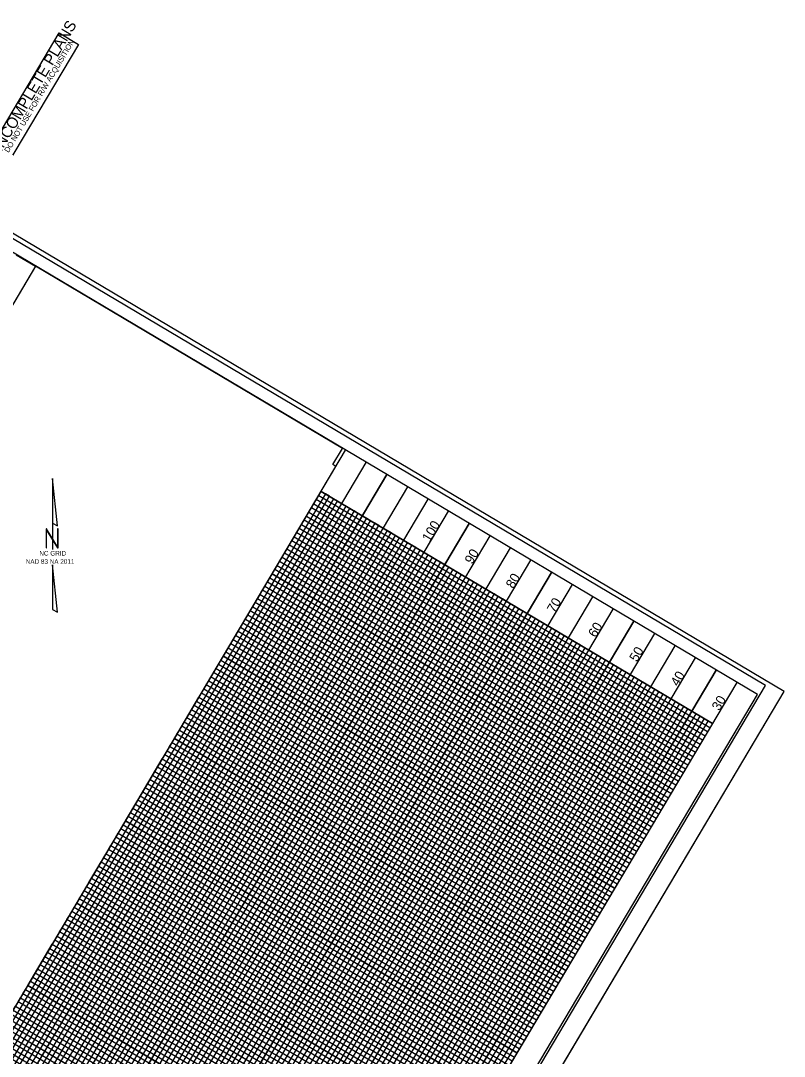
# Model space of a CAD drawing. Extents: x 2138768 to 2143723, y 406633 to 414335.
# Drawn here: x 2141936 to 2142733, y 411305 to 412387 of the extents above; entities that cross this region are included whole.
import ezdxf

# ---------------------------------------------------------------- set-up
doc = ezdxf.new("R2010")
doc.units = 0
for name, color, linetype in [('CTL North Arrow NAD 83 NA 2011 CELL', 7, 'Continuous'), ('Exist Vertical Profile Vertical Axis Label', 7, 'Continuous'), ('Sheet Clip Boundary CELL', 7, 'Continuous'), ('Sheet Cutting Line CELL', 7, 'Continuous'), ('Sheet DOT Grid CELL', 7, 'Continuous'), ('Sheet Layout Profile Border Port 2', 7, 'Continuous'), ('Sheet Plan And Profile CELL', 7, 'Continuous'), ('Sheet Plot Border Inside CELL', 7, 'Continuous'), ('Sheet Plot Border Outside CELL', 7, 'Continuous'), ('Sheet Profile Grid Major CELL', 7, 'Continuous'), ('Sheet Profile Grid Middle CELL', 7, 'Continuous'), ('Sheet Profile Grid Minor CELL', 7, 'Continuous'), ('Sheet Sticker Exception Certification CELL', 7, 'Continuous'), ('Sheet Sticker Incomplete CELL', 7, 'Continuous')]:
    doc.layers.add(name, color=color, linetype=linetype)

msp = doc.modelspace()

# ---------------------------------------------------------------- linework, layer by layer
at = {"layer": 'CTL North Arrow NAD 83 NA 2011 CELL'}
msp.add_line((2141969.1, 411838.7), (2141969.1, 411838.7), dxfattribs=at)
for points in [[(2141969, 411908.5), (2141969, 411861.9), (2141974.5, 411859.1)], [(2141962.4, 411836.1), (2141963, 411836.1), (2141963, 411854.8), (2141974.5, 411836.1), (2141975.1, 411836.1), (2141975.1, 411855.9), (2141974.5, 411855.9), (2141974.5, 411837.2), (2141963, 411855.9), (2141962.4, 411855.9)], [(2141969, 411771.9), (2141974.5, 411769.1), (2141969, 411818.5)]]:
    msp.add_lwpolyline(points, close=True, dxfattribs=at)
msp.add_lwpolyline([(2141969, 411861.9), (2141969, 411834.4)], dxfattribs=at)
at = {"layer": 'Sheet Clip Boundary CELL'}
msp.add_lwpolyline([(2141532, 410686.1), (2141538.9, 410697.6), (2142265.1, 411921.2), (2142261.9, 411923.1), (2142271.9, 411940), (2141951.4, 412130.3), (2141849.3, 411958.2), (2141755.1, 412014.2), (2141652.8, 411841.9), (2141597.8, 411874.5), (2141065.9, 410978.3)], close=True, dxfattribs=at)
at = {"layer": 'Sheet Cutting Line CELL'}
msp.add_line((2141873.9, 410238.4), (2142733.2, 411686.1), dxfattribs=at)
at = {"layer": 'Sheet DOT Grid CELL'}
for p, q in [((2141509.6, 410648.2), (2142275.2, 411938.1)), ((2141552.6, 410622.7), (2142318.2, 411912.6)), ((2142249.7, 411895.1), (2142658.1, 411652.7)), ((2141595.6, 410597.2), (2142361.2, 411887.1)), ((2141638.6, 410571.7), (2142404.2, 411861.6)), ((2142224.1, 411852.1), (2142632.6, 411609.7)), ((2141681.6, 410546.1), (2142447.2, 411836.1)), ((2141724.5, 410520.6), (2142490.2, 411810.5)), ((2142198.6, 411809.1), (2142607.1, 411566.7)), ((2141767.5, 410495.1), (2142533.2, 411785)), ((2141810.5, 410469.6), (2142576.1, 411759.5)), ((2142173.1, 411766.1), (2142581.6, 411523.7)), ((2141853.5, 410444.1), (2142619.1, 411734)), ((2142147.6, 411723.1), (2142556, 411480.7)), ((2141896.5, 410418.5), (2142662.1, 411708.5)), ((2142122, 411680.2), (2142530.5, 411437.7)), ((2142096.5, 411637.2), (2142505, 411394.7)), ((2142071, 411594.2), (2142479.5, 411351.7)), ((2142045.5, 411551.2), (2142454, 411308.7)), ((2142020, 411508.2), (2142428.4, 411265.7)), ((2141994.4, 411465.2), (2142402.9, 411222.7)), ((2141968.9, 411422.2), (2142377.4, 411179.7)), ((2141943.4, 411379.2), (2142351.9, 411136.7)), ((2141917.9, 411336.2), (2142326.4, 411093.7))]:
    msp.add_line(p, q, dxfattribs=at)
at = {"layer": 'Sheet Layout Profile Border Port 2'}
msp.add_lwpolyline([(2141535.1, 410691.2), (2142249.7, 411895.1), (2142658.1, 411652.7), (2141943.6, 410448.8)], close=True, dxfattribs=at)
at = {"layer": 'Sheet Plan And Profile CELL'}
msp.add_line((2142683.6, 411695.7), (2141918, 410405.8), dxfattribs=at)
msp.add_lwpolyline([(2141802.2, 412218.9), (2141036.6, 410929), (2141939.5, 410393), (2142705.1, 411682.9)], close=True, dxfattribs=at)
at = {"layer": 'Sheet Plot Border Inside CELL'}
msp.add_lwpolyline([(2141863.3, 410259.8), (2142713.7, 411692.4), (2141806.4, 412230.9), (2140956.1, 410798.2)], close=True, dxfattribs=at)
at = {"layer": 'Sheet Plot Border Outside CELL'}
msp.add_lwpolyline([(2141873.9, 410238.4), (2142733.2, 411686.1), (2141791.5, 412245), (2140932.3, 410797.3)], close=True, dxfattribs=at)
at = {"layer": 'Sheet Profile Grid Major CELL'}
for points in [[(2141509.6, 410648.2), (2142275.2, 411938.1)], [(2142318.2, 411912.6), (2141552.6, 410622.7), (2141595.6, 410597.2), (2142361.2, 411887.1)], [(2142658.1, 411652.7), (2142249.7, 411895.1)], [(2142404.2, 411861.6), (2141638.6, 410571.7), (2141681.6, 410546.1), (2142447.2, 411836.1)], [(2142607.1, 411566.7), (2142198.6, 411809.1), (2142224.1, 411852.1), (2142632.6, 411609.7)], [(2142490.2, 411810.5), (2141724.5, 410520.6), (2141767.5, 410495.1), (2142533.2, 411785)], [(2142576.1, 411759.5), (2141810.5, 410469.6), (2141853.5, 410444.1), (2142619.1, 411734)], [(2142556, 411480.7), (2142147.6, 411723.1), (2142173.1, 411766.1), (2142581.6, 411523.7)], [(2142662.1, 411708.5), (2141896.5, 410418.5)], [(2142505, 411394.7), (2142096.5, 411637.2), (2142122, 411680.2), (2142530.5, 411437.7)], [(2142454, 411308.7), (2142045.5, 411551.2), (2142071, 411594.2), (2142479.5, 411351.7)], [(2142402.9, 411222.7), (2141994.4, 411465.2), (2142020, 411508.2), (2142428.4, 411265.7)], [(2142351.9, 411136.7), (2141943.4, 411379.2), (2141968.9, 411422.2), (2142377.4, 411179.7)], [(2142300.8, 411050.7), (2141892.4, 411293.2), (2141917.9, 411336.2), (2142326.4, 411093.7)]]:
    msp.add_lwpolyline(points, dxfattribs=at)
at = {"layer": 'Sheet Profile Grid Middle CELL'}
for p, q in [((2141531.1, 410635.5), (2142296.7, 411925.4)), ((2142339.7, 411899.9), (2141574.1, 410609.9)), ((2141617.1, 410584.4), (2142382.7, 411874.3)), ((2142425.7, 411848.8), (2141660.1, 410558.9)), ((2141703.1, 410533.4), (2142468.7, 411823.3)), ((2142511.7, 411797.8), (2141746, 410507.9)), ((2141789, 410482.3), (2142554.6, 411772.3)), ((2142597.6, 411746.7), (2141832, 410456.8)), ((2141875, 410431.3), (2142640.6, 411721.2))]:
    msp.add_line(p, q, dxfattribs=at)
for points in [[(2142619.8, 411588.2), (2142211.4, 411830.6), (2142236.9, 411873.6), (2142645.4, 411631.2)], [(2142568.8, 411502.2), (2142160.3, 411744.6), (2142185.9, 411787.6), (2142594.3, 411545.2)], [(2142517.8, 411416.2), (2142109.3, 411658.7), (2142134.8, 411701.6), (2142543.3, 411459.2)], [(2142466.7, 411330.2), (2142058.2, 411572.7), (2142083.8, 411615.7), (2142492.2, 411373.2)], [(2142415.7, 411244.2), (2142007.2, 411486.7), (2142032.7, 411529.7), (2142441.2, 411287.2)], [(2142364.6, 411158.2), (2141956.2, 411400.7), (2141981.7, 411443.7), (2142390.2, 411201.2)], [(2142313.6, 411072.2), (2141905.1, 411314.7), (2141930.6, 411357.7), (2142339.1, 411115.2)]]:
    msp.add_lwpolyline(points, dxfattribs=at)
at = {"layer": 'Sheet Profile Grid Minor CELL'}
for points in [[(2141543.7, 410686.1), (2142258.3, 411890), (2142254, 411892.6), (2141539.4, 410688.7)], [(2142653, 411644.1), (2142244.5, 411886.5), (2142247.1, 411890.8), (2142655.6, 411648.4)], [(2141552.3, 410681), (2142266.8, 411884.9), (2142262.5, 411887.5), (2141548, 410683.6)], [(2141565.2, 410673.4), (2142279.7, 411877.3), (2142275.4, 411879.8), (2141560.9, 410675.9)], [(2142647.9, 411635.5), (2142239.4, 411877.9), (2142242, 411882.2), (2142650.5, 411639.8)], [(2141573.8, 410668.3), (2142288.3, 411872.2), (2142284, 411874.7), (2141569.5, 410670.8)], [(2142640.3, 411622.6), (2142231.8, 411865), (2142234.3, 411869.3), (2142642.8, 411626.9)], [(2141586.7, 410660.6), (2142301.2, 411864.5), (2142296.9, 411867.1), (2141582.4, 410663.2)], [(2141595.3, 410655.5), (2142309.8, 411859.4), (2142305.5, 411862), (2141591, 410658.1)], [(2142635.2, 411614), (2142226.7, 411856.4), (2142229.2, 411860.7), (2142637.7, 411618.3)], [(2141608.2, 410647.8), (2142322.7, 411851.8), (2142318.4, 411854.3), (2141603.9, 410650.4)], [(2141616.8, 410642.7), (2142331.3, 411846.6), (2142327, 411849.2), (2141612.5, 410645.3)], [(2142627.5, 411601.1), (2142219, 411843.5), (2142221.6, 411847.8), (2142630, 411605.4)], [(2141625.4, 410637.6), (2142339.9, 411841.5)], [(2141634, 410632.5), (2142348.5, 411836.4), (2142344.2, 411839), (2141629.7, 410635.1)], [(2142622.4, 411592.5), (2142213.9, 411834.9), (2142216.5, 411839.2), (2142624.9, 411596.8)], [(2141646.9, 410624.9), (2142361.4, 411828.8), (2142352.8, 411833.9), (2141638.3, 410630)], [(2141655.5, 410619.8), (2142370, 411823.7), (2142365.7, 411826.2), (2141651.2, 410622.3)], [(2142614.7, 411579.6), (2142206.3, 411822), (2142208.8, 411826.3), (2142617.3, 411583.9)], [(2141668.4, 410612.1), (2142382.9, 411816), (2142374.3, 411821.1), (2141659.8, 410617.2)], [(2142609.6, 411571), (2142201.2, 411813.4), (2142203.7, 411817.7), (2142612.2, 411575.3)], [(2141677, 410607), (2142391.5, 411810.9), (2142387.2, 411813.5), (2141672.7, 410609.6)], [(2141689.9, 410599.4), (2142404.4, 411803.3), (2142395.8, 411808.4), (2141681.3, 410604.5)], [(2142602, 411558.1), (2142193.5, 411800.5), (2142196.1, 411804.8), (2142604.5, 411562.4)], [(2141698.5, 410594.2), (2142413, 411798.2), (2142408.7, 411800.7), (2141694.2, 410596.8)], [(2141711.4, 410586.6), (2142425.9, 411790.5), (2142417.3, 411795.6), (2141702.8, 410591.7)], [(2142596.9, 411549.5), (2142188.4, 411791.9), (2142191, 411796.2), (2142599.4, 411553.8)], [(2141720, 410581.5), (2142434.5, 411785.4), (2142430.2, 411788), (2141715.7, 410584)], [(2141732.9, 410573.8), (2142447.4, 411777.7), (2142438.8, 411782.8), (2141724.3, 410578.9)], [(2142589.2, 411536.6), (2142180.7, 411779), (2142183.3, 411783.3), (2142591.8, 411540.9)], [(2141741.5, 410568.7), (2142456, 411772.6), (2142451.7, 411775.2), (2141737.2, 410571.3)], [(2142584.1, 411528), (2142175.6, 411770.4), (2142178.2, 411774.7), (2142586.7, 411532.3)], [(2141754.4, 410561.1), (2142468.9, 411765), (2142460.3, 411770.1), (2141745.8, 410566.2)], [(2141763, 410556), (2142477.5, 411759.9), (2142473.2, 411762.4), (2141758.7, 410558.5)], [(2142576.5, 411515.1), (2142168, 411757.5), (2142170.5, 411761.8), (2142579, 411519.4)], [(2141775.9, 410548.3), (2142490.4, 411752.2), (2142481.8, 411757.3), (2141767.3, 410553.4)], [(2141784.5, 410543.2), (2142499, 411747.1), (2142494.7, 411749.7), (2141780.2, 410545.8)], [(2142571.4, 411506.5), (2142162.9, 411748.9), (2142165.4, 411753.2), (2142573.9, 411510.8)], [(2141797.4, 410535.6), (2142511.9, 411739.5), (2142503.3, 411744.6), (2141788.8, 410540.7)], [(2142563.7, 411493.6), (2142155.2, 411736), (2142157.8, 411740.3), (2142566.2, 411497.9)], [(2141806, 410530.4), (2142520.5, 411734.4), (2142516.2, 411736.9), (2141801.7, 410533)], [(2141818.9, 410522.8), (2142533.4, 411726.7), (2142524.8, 411731.8), (2141810.3, 410527.9)], [(2142558.6, 411485), (2142150.1, 411727.4), (2142152.7, 411731.7), (2142561.1, 411489.3)], [(2141827.5, 410517.7), (2142542, 411721.6), (2142537.7, 411724.1), (2141823.2, 410520.2)], [(2141840.4, 410510), (2142554.9, 411713.9), (2142546.3, 411719), (2141831.8, 410515.1)], [(2142550.9, 411472.1), (2142142.5, 411714.5), (2142145, 411718.8), (2142553.5, 411476.4)], [(2141849, 410504.9), (2142563.5, 411708.8), (2142559.2, 411711.4), (2141844.7, 410507.5)], [(2141861.9, 410497.3), (2142576.4, 411701.2), (2142567.8, 411706.3), (2141853.3, 410502.4)], [(2142545.8, 411463.5), (2142137.4, 411705.9), (2142139.9, 411710.2), (2142548.4, 411467.8)], [(2141870.5, 410492.2), (2142585, 411696.1), (2142580.7, 411698.6), (2141866.2, 410494.7)], [(2142538.2, 411450.6), (2142129.7, 411693.1), (2142132.3, 411697.4), (2142540.7, 411454.9)], [(2141883.4, 410484.5), (2142597.9, 411688.4), (2142589.3, 411693.5), (2141874.8, 410489.6)], [(2141939.3, 410451.3), (2142653.8, 411655.2), (2142649.5, 411657.8), (2141935, 410453.9), (2141930.7, 410456.4), (2142645.2, 411660.3), (2142640.9, 411662.9), (2141926.4, 410459), (2141922.1, 410461.5), (2141917.8, 410464.1), (2142632.3, 411668), (2142628, 411670.6), (2141913.5, 410466.6), (2141909.2, 410469.2), (2142623.7, 411673.1), (2142619.4, 411675.7), (2141904.9, 410471.8), (2141900.6, 410474.3), (2141896.3, 410476.9), (2142610.8, 411680.8), (2142606.5, 411683.3), (2141892, 410479.4), (2141887.7, 410482), (2142602.2, 411685.9)], [(2142533.1, 411442), (2142124.6, 411684.5), (2142127.2, 411688.8), (2142535.6, 411446.3)], [(2142525.4, 411429.1), (2142116.9, 411671.6), (2142119.5, 411675.9), (2142528, 411433.4)], [(2142520.3, 411420.5), (2142111.8, 411663), (2142114.4, 411667.3), (2142522.9, 411424.8)], [(2142512.7, 411407.6), (2142104.2, 411650.1), (2142106.7, 411654.4), (2142515.2, 411411.9)], [(2142507.6, 411399), (2142099.1, 411641.5), (2142101.6, 411645.8), (2142510.1, 411403.3)], [(2142499.9, 411386.1), (2142091.4, 411628.6), (2142094, 411632.9), (2142502.4, 411390.4)], [(2142494.8, 411377.5), (2142086.3, 411620), (2142088.9, 411624.3), (2142497.3, 411381.8)], [(2142487.1, 411364.6), (2142078.7, 411607.1), (2142081.2, 411611.4), (2142489.7, 411368.9)], [(2142482, 411356), (2142073.6, 411598.5), (2142076.1, 411602.8), (2142484.6, 411360.3)], [(2142474.4, 411343.1), (2142065.9, 411585.6), (2142068.5, 411589.9), (2142476.9, 411347.4)], [(2142469.3, 411334.5), (2142060.8, 411577), (2142063.4, 411581.3), (2142471.8, 411338.8)], [(2142461.6, 411321.6), (2142053.1, 411564.1), (2142055.7, 411568.4), (2142464.2, 411325.9)], [(2142456.5, 411313), (2142048, 411555.5), (2142050.6, 411559.8), (2142459.1, 411317.3)], [(2142448.9, 411300.1), (2142040.4, 411542.6), (2142042.9, 411546.9), (2142451.4, 411304.4)], [(2142443.8, 411291.5), (2142035.3, 411534), (2142037.8, 411538.3), (2142446.3, 411295.8)], [(2142436.1, 411278.6), (2142027.6, 411521.1), (2142030.2, 411525.4), (2142438.6, 411282.9)], [(2142431, 411270), (2142022.5, 411512.5), (2142025.1, 411516.8), (2142433.5, 411274.3)], [(2142423.3, 411257.1), (2142014.9, 411499.6), (2142017.4, 411503.9), (2142425.9, 411261.4)], [(2142418.2, 411248.5), (2142009.8, 411491), (2142012.3, 411495.3), (2142420.8, 411252.8)], [(2142410.6, 411235.6), (2142002.1, 411478.1), (2142004.7, 411482.4), (2142413.1, 411239.9)], [(2142405.5, 411227), (2141997, 411469.5), (2141999.6, 411473.8), (2142408, 411231.3)], [(2142397.8, 411214.1), (2141989.3, 411456.6), (2141991.9, 411460.9), (2142400.4, 411218.4)], [(2142392.7, 411205.5), (2141984.2, 411448), (2141986.8, 411452.3), (2142395.3, 411209.8)], [(2142385.1, 411192.6), (2141976.6, 411435.1), (2141979.1, 411439.4), (2142387.6, 411196.9)], [(2142379.9, 411184), (2141971.5, 411426.5), (2141974, 411430.8), (2142382.5, 411188.3)], [(2142372.3, 411171.1), (2141963.8, 411413.6), (2141966.4, 411417.9), (2142374.8, 411175.4)], [(2142367.2, 411162.5), (2141958.7, 411405), (2141961.3, 411409.3), (2142369.7, 411166.8)], [(2142359.5, 411149.6), (2141951.1, 411392.1), (2141953.6, 411396.4), (2142362.1, 411153.9)], [(2142354.4, 411141), (2141946, 411383.5), (2141948.5, 411387.8), (2142357, 411145.3)], [(2142346.8, 411128.1), (2141938.3, 411370.6), (2141940.9, 411374.9), (2142349.3, 411132.4)], [(2142341.7, 411119.5), (2141933.2, 411362), (2141935.8, 411366.3), (2142344.2, 411123.8)], [(2142334, 411106.6), (2141925.5, 411349.1), (2141928.1, 411353.4), (2142336.6, 411110.9)], [(2142328.9, 411098), (2141920.4, 411340.5), (2141923, 411344.8), (2142331.5, 411102.3)], [(2142321.3, 411085.1), (2141912.8, 411327.6), (2141915.3, 411331.9), (2142323.8, 411089.4)], [(2142316.1, 411076.5), (2141907.7, 411319), (2141910.2, 411323.3), (2142318.7, 411080.8)]]:
    msp.add_lwpolyline(points, dxfattribs=at)
at = {"layer": 'Sheet Sticker Exception Certification CELL'}
for p, q in [((2141931.2, 412142.3), (2141951.5, 412130.3)), ((2141951.4, 412130.3), (2141849.3, 411958.2))]:
    msp.add_line(p, q, dxfattribs=at)
at = {"layer": 'Sheet Sticker Incomplete CELL'}
msp.add_lwpolyline([(2141921.2, 412235.5), (2141901, 412247.5), (2141976, 412373.9), (2141996.2, 412361.9)], close=True, dxfattribs=at)

# ---------------------------------------------------------------- texts
at = {"layer": 'CTL North Arrow NAD 83 NA 2011 CELL'}
for s, p in [('NAD 83 NA 2011', (2141941.2, 411819.5)), ('NC GRID', (2141955.4, 411828.1))]:
    msp.add_text(s, height=4.8, dxfattribs=at).set_placement(p)
at = {"layer": 'Exist Vertical Profile Vertical Axis Label'}
for s, p in [('100', (2142362.9, 411841.5)), ('90', (2142407.3, 411818.4)), ('80', (2142450.3, 411792.9)), ('70', (2142493.3, 411767.4)), ('60', (2142536.3, 411741.8)), ('50', (2142579.3, 411716.3)), ('40', (2142622.3, 411690.8)), ('30', (2142665.3, 411665.3))]:
    msp.add_text(s, height=10, rotation=59.3093, dxfattribs=at).set_placement(p)
at = {"layer": 'Sheet Sticker Incomplete CELL'}
for s, height, p in [('INCOMPLETE PLANS', 11.52, (2141915.7, 412249.2)), ('DO NOT USE FOR R/W ACQUISITION', 5.76, (2141923.3, 412248.4))]:
    msp.add_text(s, height=height, rotation=59.3093, dxfattribs=at).set_placement(p)

doc.saveas('drawing.dxf')
